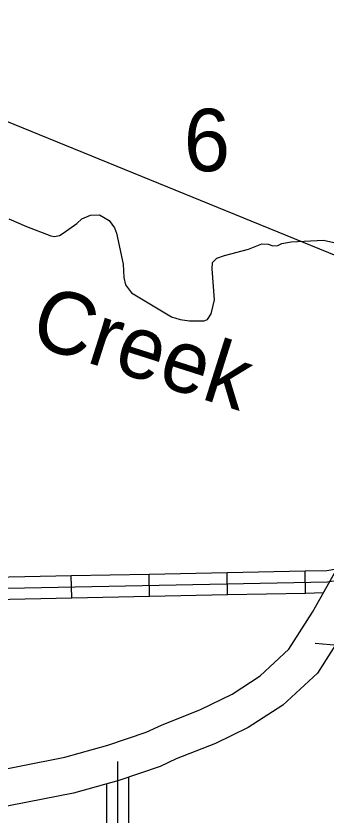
# Model space of a CAD drawing. Extents: x 1212896 to 1368412, y 378476 to 478763.
# Drawn here: x 1280046 to 1282147, y 399509 to 404923 of the extents above; entities that cross this region are included whole.
import ezdxf

# ---------------------------------------------------------------- set-up
doc = ezdxf.new("R2010")
doc.units = 0
for name, color, linetype in [('Level 10', 7, 'Continuous'), ('Level 31', 7, 'Continuous'), ('Level 32', 7, 'Continuous'), ('Level 35', 7, 'Continuous'), ('Level 45', 7, 'Continuous'), ('Level 5', 7, 'Continuous'), ('R_Draft', 7, 'Continuous')]:
    doc.layers.add(name, color=color, linetype=linetype)

msp = doc.modelspace()

# ---------------------------------------------------------------- linework, layer by layer
at = {"layer": 'Level 10'}
for points in [[(1281510.4, 400333.1), (1281700.2, 400457.4), (1281895.9, 400637.9), (1282055.1, 400887.5), (1282223.8, 401189.7), (1282401.8, 401483), (1282511.4, 401672.7), (1282530.2, 401719.5), (1282610.1, 402108.4), (1282704.7, 402496.6), (1282741.9, 402607), (1282785, 402723.4), (1282996.3, 403241.1), (1283100.2, 403515.5)], [(1283334.4, 403428), (1283229, 403149.6), (1283018, 402632.7), (1282977.6, 402523.7), (1282945.1, 402427), (1282854, 402053.6), (1282770.5, 401647.2), (1282736.8, 401563.1), (1282617, 401355.6), (1282439.9, 401063.9), (1282269.8, 400759.2), (1282089.3, 400476.1), (1281854.1, 400259.2), (1281619.9, 400108.4)], [(1277569.3, 399199.2), (1277662, 399230.1), (1277830.5, 399293), (1277923.2, 399337), (1277991.8, 399373.9), (1278101.7, 399445.2), (1278247.9, 399524.8), (1278362.1, 399564.6), (1278452, 399587.1), (1278870.9, 399647.4), (1279280, 399722.4), (1279531.9, 399760.6), (1279761.3, 399786.4), (1280377.5, 399906.3), (1280669.7, 399988.8), (1280929.5, 400076.7), (1281032.4, 400124.8), (1281297.6, 400229.5), (1281510.4, 400333.1)], [(1281619.9, 400108.4), (1281398.4, 400000.5), (1281131.3, 399895.1), (1281022.8, 399844.3), (1280743.8, 399750), (1280435.5, 399662.9), (1279799.2, 399539.1), (1279564.6, 399512.7), (1279321.2, 399475.8), (1278911.3, 399400.6), (1278500.3, 399341.5), (1278433.7, 399324.8), (1278349.5, 399295.5), (1278229.7, 399230.3), (1278119.2, 399158.5), (1278036, 399113.9), (1277928.1, 399062.6), (1277745.3, 398994.3), (1277642.4, 398960.1)]]:
    msp.add_lwpolyline(points, dxfattribs=at)
at = {"layer": 'Level 31'}
for points in [[(1280733.7, 399878), (1280731.6, 399010.9)], [(1280809.8, 399772.3), (1280808.8, 399349.8)], [(1280659.7, 399726.2), (1280658.8, 399350.2)]]:
    msp.add_lwpolyline(points, dxfattribs=at)
at = {"layer": 'Level 32'}
for p, q in [((1280952, 400996.7), (1280948.9, 401146.7)), ((1281479.9, 401007.5), (1281476.8, 401157.5)), ((1282007.8, 401018.3), (1282004.7, 401168.3)), ((1280424.1, 400985.9), (1280421.1, 401135.9))]:
    msp.add_line(p, q, dxfattribs=at)
for points in [[(1277268.8, 400835.8), (1277323.8, 400862.8), (1277390.3, 400878.7), (1279760.3, 401046), (1282157.9, 401095), (1282240.3, 401107.2), (1282344.8, 401148)], [(1280421.1, 401135.9), (1280948.9, 401146.7)], [(1280948.9, 401146.7), (1281476.8, 401157.5)], [(1281476.8, 401157.5), (1282004.7, 401168.3)], [(1282004.7, 401168.3), (1282151.5, 401171.2), (1282219.1, 401181.2)], [(1279893.2, 401125.1), (1280421.1, 401135.9)], [(1279896.2, 400975.1), (1280424.1, 400985.9)], [(1280424.1, 400985.9), (1280952, 400996.7)], [(1280952, 400996.7), (1281479.9, 401007.5)], [(1281479.9, 401007.5), (1282007.8, 401018.3)], [(1282007.8, 401018.3), (1282129.5, 401020.8)]]:
    msp.add_lwpolyline(points, dxfattribs=at)
at = {"layer": 'Level 35'}
msp.add_lwpolyline([(1279997, 403550.6), (1280117.2, 403498.8), (1280282.4, 403434.4), (1280308.4, 403430.7), (1280341.2, 403438.1), (1280366, 403452.3), (1280459.1, 403518.5), (1280493.7, 403550.9), (1280550.3, 403574.6), (1280612.1, 403578.2), (1280677, 403539.6), (1280712.8, 403489.1), (1280728.1, 403452.2), (1280773.1, 403243.3), (1280777.4, 403152.2), (1280787.5, 403104.2), (1280829, 403049.5), (1281100, 402886.1), (1281158, 402869.7), (1281222.9, 402859.3), (1281320.7, 402859.4), (1281343.5, 402868.7), (1281368.1, 402908), (1281392, 403002.4), (1281374.9, 403211.7), (1281378.1, 403254), (1281408.1, 403285.2), (1281459, 403302.6), (1281622.9, 403344.6), (1281712.3, 403380.6), (1281755.2, 403379.1), (1281786.3, 403367.4), (1281820.2, 403370.8), (1281847, 403383.1), (1281910.3, 403395.4), (1282131, 403406.2), (1282239.9, 403381.2)], dxfattribs=at)
at = {"layer": 'Level 45'}
msp.add_lwpolyline([(1282073.5, 400679), (1282225.1, 400665.4), (1282274.2, 400654.4), (1282301.4, 400642), (1282339.2, 400602.7), (1282345.7, 400577.8), (1282343.3, 400505.6), (1282276, 399890.7), (1282280.3, 399829.6), (1282285.8, 399808.7), (1282300.1, 399794), (1282346.3, 399777.9), (1283586.7, 399779), (1283616.4, 399743.5), (1283621.8, 399636.4), (1283628.6, 399599.4), (1283678.7, 399543.4), (1283766.6, 399402), (1283779.5, 399314.1), (1283776.7, 399258.9), (1283738.5, 399089.6), (1283742.3, 399054.6), (1283753.1, 399018.8), (1283786.6, 398992.5)], dxfattribs=at)
at = {"layer": 'R_Draft'}
msp.add_line((1253661.7, 414939.5), (1283025.9, 402969.6), dxfattribs=at)

# ---------------------------------------------------------------- texts
at = {"layer": 'Level 35'}
msp.add_text('Creek', height=422.4, rotation=342.3479, dxfattribs=at).set_placement((1280125.1, 402706.6))
at = {"layer": 'Level 5'}
msp.add_text('6', height=422.4, dxfattribs=at).set_placement((1281183.2, 403872.5))

doc.saveas('drawing.dxf')
